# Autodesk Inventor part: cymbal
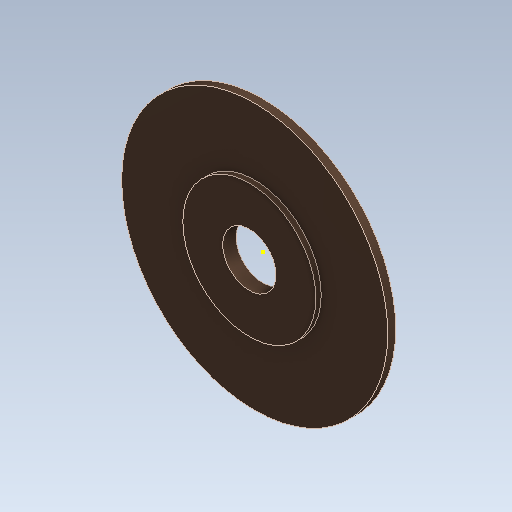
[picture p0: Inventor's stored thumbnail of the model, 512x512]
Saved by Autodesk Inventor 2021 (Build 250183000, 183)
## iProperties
Created: 2021-06
Part Number: cymbal
Material: Bronze, Cast
Document SubType Name: Modeling
Designer: adams
Density: 8.87 g/cm^3
Appearance: Bronze - Satin
Author: adams
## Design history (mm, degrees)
sketch "Sketch1"
  geometry: 1 further point
sketch "Sketch2"
  geometry: 1 further point
sketch "Sketch3"
  geometry: C1 r 127 at (0, 0); 1 further point
  constraints: 1 centre point, 1 coincident
  dimensions: "d0" = 254 diameter of C1
extrude "Extrusion1" new body sketch "Sketch3" distance "d1" = 7.62; taper "d2" = 0 deg
sketch "Sketch4"
  geometry: C1 r 63.5 at (0, 0); 1 further point
  constraints: 1 centre point, 1 coincident
  dimensions: "d3" = 127 diameter of C1
extrude "Extrusion2" join sketch "Sketch4" distance "d4" = 5.08; taper "d5" = 0 deg
sketch "Sketch5"
  geometry: C1 r 25.4 at (0, 0); 1 further point
  constraints: 1 centre point, 1 coincident
  dimensions: "d6" = 50.8 diameter of C1
extrude "Extrusion3" cut sketch "Sketch5" extent not by distance; stored distance "d7" = 0; taper "d8" = 0 deg
body "Solid1"
